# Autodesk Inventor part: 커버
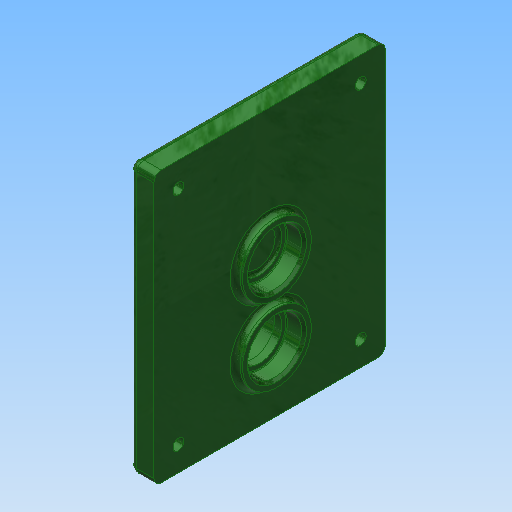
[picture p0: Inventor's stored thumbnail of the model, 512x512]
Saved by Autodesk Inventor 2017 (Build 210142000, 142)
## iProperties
Created: 2016-02
Part Number: 커버
Material: 일반
Document SubType Name: Modeling
Designer: mduedu
Density: 1 g/cm^3
Appearance: 매끄러움 - 짙은 산림 녹색
Mass: 100.23 g
Surface Area: 265.357 cm^2
Volume: 100.23 cm^3
Author: mduedu
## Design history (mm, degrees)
sketch "스케치1"
  geometry: L1 (63, 47)-(-47, 47); L2 (-47, 47)-(-47, -47); L3 (-47, -47)-(63, -47); L4 (63, -47)-(63, 47); 2 further points
  constraints: 8 end point, 2 parallel, 1 horizontal, 1 horizontal alignment, 1 midpoint, 1 perpendicular
  dimensions: "d102" = 94 distance of L3.end L1.start; "d104" = 47 distance from line of L2 point (0, 0); "d105" = 110 distance of L1.start L1.end
extrude "돌출1" new body sketch "스케치1" distance "d1" = 10; taper "d2" = 0 deg
sketch "스케치2"
  geometry: C1 r 14 at (0, 11); 1 further point
  constraints: 1 centre point, 1 vertical alignment
  dimensions: "d3" = 28 diameter of C1; "d6" = 11 distance of C1.centre point (0, 0)
extrude "돌출2" join sketch "스케치2" distance "d7" = 3; taper "d8" = 0 deg
sketch "스케치3"
  geometry: C1 r 14 at (0, -20); 1 further point
  constraints: 1 centre point, 1 vertical alignment
  dimensions: "d9" = 28 diameter of C1; "d10" = 20 distance of C1.centre point (0, 0)
extrude "돌출3" join sketch "스케치3" distance "d11" = 3; taper "d12" = 0 deg
hole "구멍1" diameter "d15" = 22; stored, may be unused: countersink angle "d19" = 90 deg, drill point angle "d21" = 0 deg; dims "d13" = 10, "d14" = 10, "d16" = 6, "d17" = 4, "d18" = 2, "d20" = 7
hole "구멍2" diameter "d24" = 18; stored, may be unused: countersink angle "d28" = 90 deg, drill point angle "d30" = 0 deg; dims "d22" = 10, "d23" = 10, "d25" = 6, "d26" = 4, "d27" = 2, "d29" = 1
hole "구멍3" diameter "d33" = 22; stored, may be unused: countersink angle "d37" = 90 deg, drill point angle "d39" = 0 deg; dims "d34" = 6, "d35" = 4, "d36" = 2, "d38" = 7, "d73" = 10, "d74" = 10
sketch "스케치4"
  geometry: C1 r 14 at (0, -20) reference; C2 r 18 at (0, -20); 1 further point
  constraints: 1 centre point, 1 coincident
  dimensions: "d40" = 36 diameter of C2
extrude "돌출4" join sketch "스케치4" distance "d41" = 4; taper "d42" = 0 deg
hole "구멍4" diameter "d45" = 22; stored, may be unused: countersink angle "d49" = 90 deg, drill point angle "d51" = 0 deg; dims "d43" = 10, "d44" = 10, "d46" = 6, "d47" = 4, "d48" = 2, "d50" = 7
hole "구멍5" diameter "d54" = 18; stored, may be unused: countersink angle "d58" = 90 deg, drill point angle "d60" = 0 deg; dims "d55" = 6, "d56" = 4, "d57" = 2, "d59" = 7, "d116" = 10, "d117" = 10
fillet "모깎기1" dims "d61" = 0.3
fillet "모깎기2" dims "d62" = 2
chamfer "모따기1" distance "d63" = 1; stored, may be unused: second distance "d64" = 2, angle "d65" = 45 deg
fillet "모깎기6" dims "d88" = 2
fillet "모깎기4" dims "d75" = 2
sketch "스케치9"
  geometry: L1 (47, 63)-(47, -47) reference; L2 (-47, 63)-(47, 63) reference; L3 (-47, -47)-(-47, 63) reference; L4 (47, -47)-(-47, -47) reference; L5 (37, 53)-(37, -37); L6 (37, -37)-(-37, -37); L7 (-37, -37)-(-37, 53); L8 (-37, 53)-(37, 53); C1 r 20 at (0, -20) reference; 5 further points
  constraints: 8 end point, 4 coincident, 3 other
  dimensions: "d107" = 10 distance between parallel lines of L8 L2
hole "구멍7" sketch "스케치9" at (-37, 53), (37, 53), (37, -37), (-37, -37) diameter "d108" = 4.5; stored, may be unused: countersink angle "d112" = 90 deg, drill point angle "d114" = 118 deg; dims "d109" = 6, "d110" = 8, "d111" = 4.6, "d113" = 8
fillet "모깎기8" dims "d106" = 3
fillet "모깎기9" dims "d115" = 3
node "솔리드1"
node "투영된 루프2"
